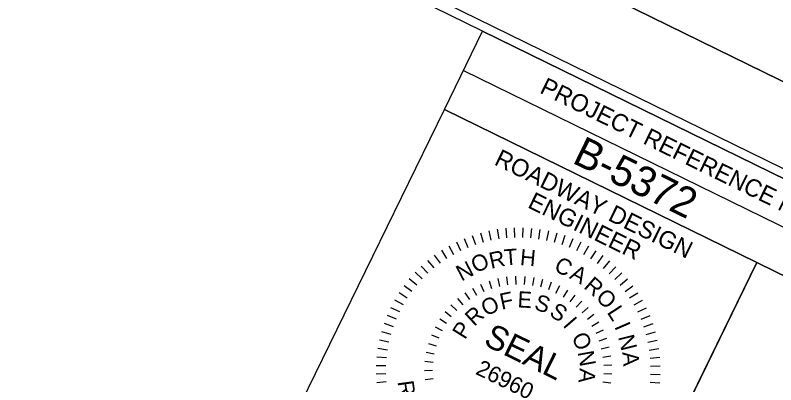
# Model space of a CAD drawing. Extents: x 1518247 to 1523638, y 635234 to 639927.
# Drawn here: x 1522580.9 to 1522799.6, y 639158.1 to 639264.3 of the extents above; entities that cross this region are included whole.
import ezdxf

# ---------------------------------------------------------------- set-up
doc = ezdxf.new("R2010")
doc.units = 0
for name, color, linetype in [('Default', 7, 'Continuous'), ('DTM TIN Hull White', 7, 'Continuous'), ('Prop Dimension Text', 7, 'Continuous'), ('Sheet Cutting Line CELL', 7, 'Continuous'), ('Sheet Plot Border Inside CELL', 7, 'Continuous'), ('Sheet Plot Border Outside CELL', 7, 'Continuous'), ('Sheet Typical CELL', 7, 'Continuous')]:
    doc.layers.add(name, color=color, linetype=linetype)

msp = doc.modelspace()

# ---------------------------------------------------------------- linework, layer by layer
at = {"layer": 'Default'}
msp.add_lwpolyline([(1522438.02, 638198.63), (1520925.25, 638938.49), (1521408.53, 639926.64), (1522921.3, 639186.78)], close=True, dxfattribs=at)
at = {"layer": 'DTM TIN Hull White'}
for p, q in [((1522717.1, 639202.36), (1522717.67, 639199.64)), ((1522719.52, 639202.8), (1522719.94, 639200.05)), ((1522721.97, 639203.09), (1522722.22, 639200.32)), ((1522724.44, 639203.24), (1522724.52, 639200.45)), ((1522726.91, 639203.22), (1522726.82, 639200.44)), ((1522729.38, 639203.07), (1522729.12, 639200.3)), ((1522731.82, 639202.77), (1522731.39, 639200.01)), ((1522734.25, 639202.32), (1522733.66, 639199.6)), ((1522710.03, 639200.18), (1522711.08, 639197.6)), ((1522712.34, 639201.05), (1522713.24, 639198.41)), ((1522714.69, 639201.78), (1522715.44, 639199.09)), ((1522736.65, 639201.72), (1522735.89, 639199.04)), ((1522739, 639200.98), (1522738.09, 639198.35)), ((1522741.31, 639200.1), (1522740.23, 639197.53)), ((1522705.58, 639198.03), (1522706.94, 639195.6)), ((1522707.77, 639199.17), (1522708.98, 639196.67)), ((1522743.56, 639199.08), (1522742.33, 639196.57)), ((1522745.74, 639197.92), (1522744.37, 639195.5)), ((1522703.47, 639196.76), (1522704.97, 639194.42)), ((1522747.85, 639196.64), (1522746.33, 639194.3)), ((1522699.48, 639193.84), (1522701.26, 639191.7)), ((1522701.43, 639195.36), (1522703.07, 639193.11)), ((1522749.88, 639195.23), (1522748.22, 639192.99)), ((1522751.82, 639193.71), (1522750.03, 639191.57)), ((1522697.63, 639192.21), (1522699.53, 639190.18)), ((1522753.67, 639192.06), (1522751.75, 639190.04)), ((1522695.88, 639190.47), (1522697.9, 639188.56)), ((1522722.23, 639189.11), (1522722.51, 639186.8)), ((1522724.82, 639189.3), (1522724.89, 639186.98)), ((1522727.43, 639189.25), (1522727.27, 639186.93)), ((1522755.4, 639190.31), (1522753.37, 639188.41)), ((1522694.23, 639188.63), (1522696.37, 639186.84)), ((1522714.72, 639187.04), (1522715.66, 639184.91)), ((1522717.16, 639187.97), (1522717.88, 639185.76)), ((1522719.66, 639188.66), (1522720.17, 639186.39)), ((1522730.01, 639188.95), (1522729.63, 639186.65)), ((1522732.56, 639188.39), (1522731.95, 639186.15)), ((1522735.03, 639187.59), (1522734.22, 639185.42)), ((1522757.03, 639188.46), (1522754.89, 639186.68)), ((1522691.3, 639184.66), (1522693.64, 639183.14)), ((1522692.71, 639186.69), (1522694.95, 639185.03)), ((1522712.39, 639185.88), (1522713.53, 639183.85)), ((1522737.42, 639186.56), (1522736.4, 639184.48)), ((1522736.4, 639184.48), (1522737.42, 639186.56)), ((1522739.7, 639185.3), (1522738.49, 639183.33)), ((1522758.55, 639186.51), (1522756.3, 639184.87)), ((1522690.02, 639182.55), (1522692.44, 639181.18)), ((1522708.12, 639182.91), (1522709.63, 639181.14)), ((1522710.19, 639184.5), (1522711.51, 639182.59)), ((1522741.85, 639183.84), (1522740.45, 639181.98)), ((1522759.95, 639184.47), (1522757.61, 639182.97)), ((1522688.86, 639180.37), (1522691.37, 639179.14)), ((1522706.22, 639181.13), (1522707.89, 639179.51)), ((1522743.85, 639182.17), (1522742.27, 639180.46)), ((1522745.67, 639180.31), (1522743.94, 639178.76)), ((1522761.22, 639182.36), (1522758.79, 639181)), ((1522687.84, 639178.12), (1522690.41, 639177.04)), ((1522704.5, 639179.17), (1522706.32, 639177.73)), ((1522747.31, 639178.28), (1522745.44, 639176.91)), ((1522762.36, 639180.17), (1522759.86, 639178.96)), ((1522702.98, 639177.06), (1522704.93, 639175.8)), ((1522748.74, 639176.11), (1522746.74, 639174.92)), ((1522763.37, 639177.91), (1522760.8, 639176.86)), ((1522686.96, 639175.81), (1522689.59, 639174.89)), ((1522701.67, 639174.81), (1522703.73, 639173.74)), ((1522749.96, 639173.81), (1522747.85, 639172.82)), ((1522764.24, 639175.6), (1522761.6, 639174.7)), ((1522686.22, 639173.46), (1522688.9, 639172.7)), ((1522700.58, 639172.45), (1522702.73, 639171.58)), ((1522764.97, 639173.25), (1522762.28, 639172.5)), ((1522685.62, 639171.06), (1522688.34, 639170.47)), ((1522699.73, 639169.99), (1522701.95, 639169.34)), ((1522750.95, 639171.4), (1522748.76, 639170.62)), ((1522765.55, 639170.84), (1522762.83, 639170.27)), ((1522685.17, 639168.63), (1522687.93, 639168.2)), ((1522699.11, 639167.46), (1522701.39, 639167.02)), ((1522751.7, 639168.91), (1522749.45, 639168.35)), ((1522765.99, 639168.42), (1522763.24, 639168)), ((1522684.87, 639166.18), (1522687.64, 639165.93)), ((1522752.21, 639166.36), (1522749.91, 639166.01)), ((1522766.28, 639165.97), (1522763.51, 639165.72)), ((1522684.72, 639163.72), (1522687.5, 639163.63)), ((1522698.74, 639164.88), (1522701.05, 639164.67)), ((1522752.47, 639163.77), (1522750.15, 639163.64)), ((1522766.43, 639163.5), (1522763.64, 639163.42)), ((1522684.7, 639161.25), (1522687.49, 639161.33)), ((1522698.63, 639162.28), (1522700.95, 639162.29)), ((1522752.48, 639161.16), (1522750.16, 639161.27)), ((1522766.42, 639161.03), (1522763.63, 639161.12)), ((1522684.85, 639158.78), (1522687.62, 639159.03)), ((1522698.76, 639159.69), (1522701.07, 639159.91)), ((1522752.23, 639158.57), (1522749.94, 639158.9)), ((1522766.27, 639158.56), (1522763.49, 639158.82))]:
    msp.add_line(p, q, dxfattribs=at)
at = {"layer": 'Sheet Cutting Line CELL'}
msp.add_line((1522921.3, 639186.78), (1521408.53, 639926.64), dxfattribs=at)
at = {"layer": 'Sheet Plot Border Inside CELL'}
msp.add_lwpolyline([(1522907.39, 639168.59), (1521410.35, 639900.76), (1520946.79, 638952.95), (1522443.84, 638220.77)], close=True, dxfattribs=at)
at = {"layer": 'Sheet Plot Border Outside CELL'}
msp.add_lwpolyline([(1522921.3, 639186.78), (1521408.53, 639926.64), (1520925.25, 638938.49), (1522438.02, 638198.63)], close=True, dxfattribs=at)
at = {"layer": 'Sheet Typical CELL'}
for p, q in [((1522709.82, 639248.41), (1522889.53, 639160.52)), ((1522794.21, 639193.22), (1522744.8, 639092.21))]:
    msp.add_line(p, q, dxfattribs=at)
for points in [[(1522895.04, 639171.79), (1521547.57, 639830.81), (1521086.25, 638887.58), (1522433.73, 638228.56)], [(1522715.33, 639259.68), (1522895.04, 639171.79), (1522884.04, 639149.29), (1522704.33, 639237.18)], [(1522704.33, 639237.18), (1522794.21, 639193.22), (1522744.78, 639092.16), (1522654.9, 639136.12)], [(1522794.21, 639193.22), (1522884.04, 639149.29), (1522834.61, 639048.23), (1522744.78, 639092.16)]]:
    msp.add_lwpolyline(points, close=True, dxfattribs=at)

# ---------------------------------------------------------------- texts
at = {"layer": 'DTM TIN Hull White'}
for s, height, rotation, p in [('O', 4.64, 25.602, (1522713.36, 639190.09)), ('R', 4.64, 12.5453, (1522717.75, 639191.42)), ('T', 4.64, 4.3843, (1522721.69, 639192.38)), ('H', 4.64, 354.9524, (1522725.94, 639192.55)), ('N', 4.64, 27.5614, (1522709.24, 639187.75)), ('C', 4.64, 331.2417, (1522735.54, 639191.16)), ('A', 4.64, 331.2417, (1522740.05, 639188.84)), ('R', 4.64, 319.2324, (1522744.17, 639186.07)), ('F', 4.64, 12.1253, (1522720.79, 639179.66)), ('E', 4.64, 356.8291, (1522725.28, 639180.39)), ('O', 4.64, 316.1756, (1522747.62, 639182.89)), ('O', 4.64, 27.4216, (1522716.37, 639177.66)), ('S', 4.64, 341.5328, (1522729.89, 639179.9)), ('R', 4.64, 42.7178, (1522712.89, 639174.73)), ('S', 4.64, 326.2366, (1522734.22, 639178.21)), ('L', 4.64, 303.0393, (1522750.94, 639178.95)), ('P', 4.64, 58.0141, (1522710.24, 639170.91)), ('I', 4.64, 310.9403, (1522738.21, 639175.14)), ('I', 4.64, 293.4638, (1522753.12, 639174.89)), ('SEAL', 6.965, 333.8847, (1522715.28, 639169.74)), ('O', 4.64, 295.6441, (1522740.78, 639171.87)), ('N', 4.64, 284.1693, (1522754.24, 639171.9)), ('N', 4.64, 280.3478, (1522742.62, 639167.5)), ('A', 4.64, 274.4018, (1522755.49, 639167.48)), ('26960', 4.64, 333.8847, (1522713.03, 639161.34)), ('A', 4.64, 265.0516, (1522743.23, 639162.97)), ('R', 4.64, 277.8197, (1522690.82, 639159.05))]:
    msp.add_text(s, height=height, rotation=rotation, dxfattribs=at).set_placement(p)
at = {"layer": 'Prop Dimension Text'}
msp.add_text('B-5372', height=8.643, rotation=333.8962, dxfattribs=at).set_placement((1522740.77, 639222.03))
at = {"layer": 'Sheet Typical CELL'}
for s, height, p in [('PROJECT REFERENCE NO.', 5.0001, (1522731.46, 639242.11)), ('ROADWAY DESIGN', 5.0001, (1522718.38, 639221.51)), ('ENGINEER', 5, (1522727.99, 639209.19))]:
    msp.add_text(s, height=height, rotation=333.9377, dxfattribs=at).set_placement(p)

doc.saveas('drawing.dxf')
